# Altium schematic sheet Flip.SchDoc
size A3; Author: Power Lin; SheetNumber: 1; SheetTotal: 1; Website: wiki-power.com
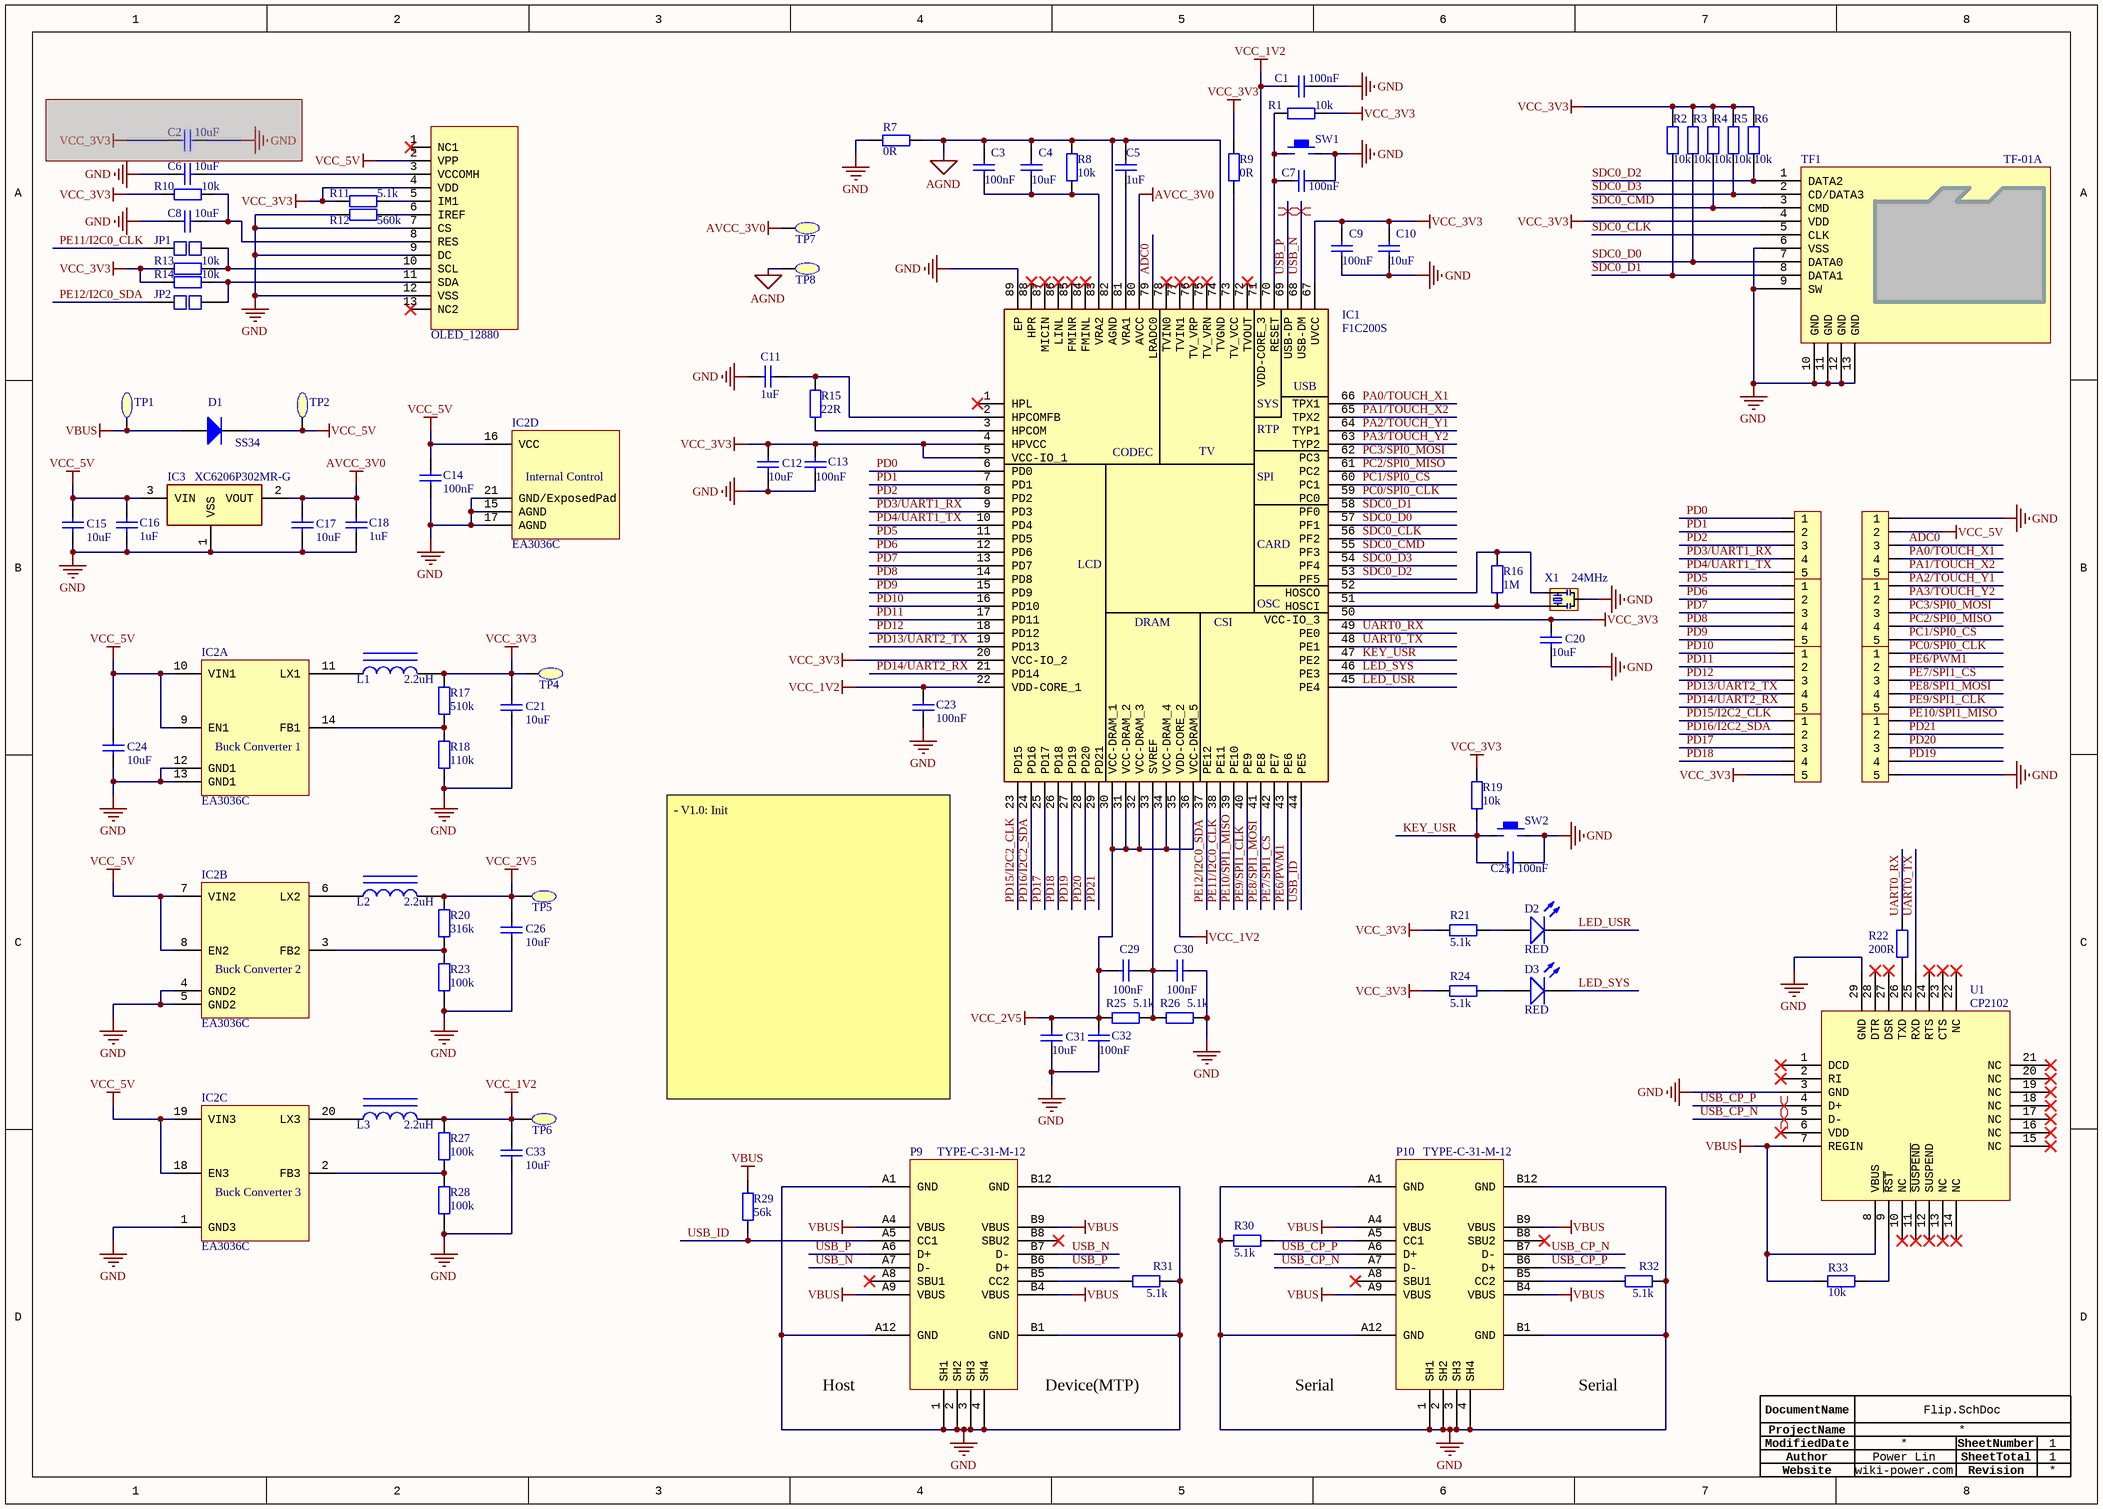
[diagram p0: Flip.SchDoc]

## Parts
C1  100nF  [CAP-0402]
C2  10uF  [CAP-0402]  (masked out: inside a compile mask, not in the netlist)
C3  100nF  [CAP-0402]
C4  10uF  [CAP-0402]
C5  1uF  [CAP-0402]
C6  10uF  [CAP-0402]
C7  100nF  [CAP-0402]
C8  10uF  [CAP-0402]
C9  100nF  [CAP-0402]
C10  10uF  [CAP-0402]
C11  1uF  [CAP-0402]
C12  10uF  [CAP-0402]
C13  100nF  [CAP-0402]
C14  100nF  [CAP-0402]
C15  10uF  [CAP-0402]
C16  1uF  [CAP-0402]
C17  10uF  [CAP-0402]
C18  1uF  [CAP-0402]
C20  10uF  [CAP-0402]
C21  10uF  [CAP-0402]
C23  100nF  [CAP-0402]
C24  10uF  [CAP-0402]
C25  100nF  [CAP-0402]
C26  10uF  [CAP-0402]
C29  100nF  [CAP-0402]
C30  100nF  [CAP-0402]
C31  10uF  [CAP-0402]
C32  100nF  [CAP-0402]
C33  10uF  [CAP-0402]
D1  SS34  [DO-214AC/SMA]
D2  RED  [LED-0402]
D3  RED  [LED-0402]
IC1  F1C200S  [QFN88P_10X10mm]
IC2  EA3036C  [QFN3mmx3mm-20]  (parts A,B,C,D of 4)
IC3  XC6206P302MR-G  [SOT-23-3]
JP1  Select  [选择焊点-0402]  (value not drawn)
JP2  Select  [选择焊点-0402]  (value not drawn)
L1  2.2uH  [L-1008]
L2  2.2uH  [L-1008]
L3  2.2uH  [L-1008]
M1  OLED_12880  [OLED_0.78INCH_12880]
P1  HDR1x5  [HDR1X5_2.54_180_BLANK]  (value not drawn)
P2  HDR1x5  [HDR1X5_2.54_180_BLANK]  (value not drawn)
P3  HDR1x5  [HDR1X5_2.54_180_BLANK]  (value not drawn)
P4  HDR1x5  [HDR1X5_2.54_180_BLANK]  (value not drawn)
P5  HDR1x5  [HDR1X5_2.54_180_BLANK]  (value not drawn)
P6  HDR1x5  [HDR1X5_2.54_180_BLANK]  (value not drawn)
P7  HDR1x5  [HDR1X5_2.54_180_BLANK]  (value not drawn)
P8  HDR1x5  [HDR1X5_2.54_180_BLANK]  (value not drawn)
P9  TYPE-C-31-M-12  [Type-C_16+4P]
P10  TYPE-C-31-M-12  [Type-C_16+4P]
R1  10k  [R-0402]
R2  10k  [R-0402]
R3  10k  [R-0402]
R4  10k  [R-0402]
R5  10k  [R-0402]
R6  10k  [R-0402]
R7  0R  [R-0402]
R8  10k  [R-0402]
R9  0R  [R-0402]
R10  10k  [R-0402]
R11  5.1k  [R-0402]
R12  560k  [R-0402]
R13  10k  [R-0402]
R14  10k  [R-0402]
R15  22R  [R-0402]
R16  1M  [R-0402]
R17  510k  [R-0402]
R18  110k  [R-0402]
R19  10k  [R-0402]
R20  316k  [R-0402]
R21  5.1k  [R-0402]
R22  200R  [R-0402]
R23  100k  [R-0402]
R24  5.1k  [R-0402]
R25  5.1k  [R-0402]
R26  5.1k  [R-0402]
R27  100k  [R-0402]
R28  100k  [R-0402]
R29  56k  [R-0402]
R30  5.1k  [R-0402]
R31  5.1k  [R-0402]
R32  5.1k  [R-0402]
R33  10k  [R-0402]
SW1  KEY  [KEY-4P-4.2*3.4*2.5]  (value not drawn)
SW2  KEY  [KEY-4P-4.2*3.4*2.5]  (value not drawn)
TF1  TF-01A  [TF_1]
TP1  TestPoint  [TestPoint]  (value not drawn)
TP2  TestPoint  [TestPoint]  (value not drawn)
TP4  TestPoint  [TestPoint]  (value not drawn)
TP5  TestPoint  [TestPoint]  (value not drawn)
TP6  TestPoint  [TestPoint]  (value not drawn)
TP7  TestPoint  [TestPoint]  (value not drawn)
TP8  TestPoint  [TestPoint]  (value not drawn)
U1  CP2102  [QFN28]
X1  24MHz  [SMD3213-3P]

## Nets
AGND: C3.1 C4.2 C5.1 IC1.74(TVGND) IC1.82(AGND) R7.1 R8.2 TP8.1
AVCC_3V0: C17.2 C18.1 IC1.80(AVCC) IC3.2(VOUT) TP7.1
GND: C1.1 C6.2 C7.1 C8.2 C9.2 C10.1 C11.1 C12.1 C13.1 C14.1 C15.1 C16.2 C17.1 C18.2 C20.1 C21.1 C23.1 C24.1 C25.1 C26.1 C30.2 C31.1 C32.1 C33.1 IC1.89(EP) IC2.1(GND3) IC2.4(GND2) IC2.5(GND2) IC2.12(GND1) IC2.13(GND1) IC2.15(AGND) IC2.17(AGND) IC2.21(GND/ExposedPad) IC3.1(VSS) M1.7(CS) M1.9(DC) M1.12(VSS) P2.1 P8.5 P9.1(SH1) P9.2(SH2) P9.3(SH3) P9.4(SH4) P9.A1(GND) P9.A12(GND) P9.B1(GND) P9.B12(GND) P10.1(SH1) P10.2(SH2) P10.3(SH3) P10.4(SH4) P10.A1(GND) P10.A12(GND) P10.B1(GND) P10.B12(GND) R7.2 R12.1 R18.1 R23.1 R26.2 R28.1 R30.2 R31.2 R32.2 SW1.2 SW2.2 TF1.6(VSS) TF1.9(SW) TF1.10(GND) TF1.11(GND) TF1.12(GND) TF1.13(GND) U1.3(GND) U1.29(GND) X1.2(GND)
VBUS: D1.1(A) P9.A4(VBUS) P9.A9(VBUS) P9.B4(VBUS) P9.B9(VBUS) P10.A4(VBUS) P10.A9(VBUS) P10.B4(VBUS) P10.B9(VBUS) R29.1 R33.2 TP1.1 U1.7(REGIN) U1.8(VBUS)
VCC_1V2: C1.2 C23.2 C33.2 IC1.22(VDD-CORE_1) IC1.35(VDD-CORE_2) IC1.71(VDD-CORE_3) L3.2 R27.2 TP6.1
VCC_2V5: C26.2 C29.1 C31.2 C32.2 IC1.30(VCC-DRAM_1) IC1.31(VCC-DRAM_2) IC1.32(VCC-DRAM_3) IC1.34(VCC-DRAM_4) IC1.36(VCC-DRAM_5) L2.2 R20.2 R25.1 TP5.1
VCC_3V3: C9.1 C10.2 C12.2 C13.2 C20.2 C21.2 IC1.4(HPVCC) IC1.5(VCC-IO_1) IC1.20(VCC-IO_2) IC1.50(VCC-IO_3) IC1.67(UVCC) L1.2 M1.4(VDD) P7.5 R1.2 R2.2 R3.2 R4.2 R5.2 R6.2 R9.2 R10.1 R11.1 R13.1 R14.1 R17.2 R19.2 R21.1 R24.1 TF1.4(VDD) TP4.1
VCC_5V: C14.2 C15.2 C16.1 C24.2 D1.2(K) IC2.7(VIN2) IC2.8(EN2) IC2.9(EN1) IC2.10(VIN1) IC2.16(VCC) IC2.18(EN3) IC2.19(VIN3) IC3.3(VIN) M1.2(VPP) P2.2 TP2.1
ADC0: IC1.79(LRADC0) P2.3
KEY_USR: C25.2 IC1.47(PE2) R19.1 SW2.1
LED_SYS: D3.K IC1.46(PE3)
LED_USR: D2.K IC1.45(PE4)
PA0/TOUCH_X1: IC1.66(TPX1) P2.4
PA1/TOUCH_X2: IC1.65(TPX2) P2.5
PA2/TOUCH_Y1: IC1.64(TYP1) P4.1
PA3/TOUCH_Y2: IC1.63(TYP2) P4.2
PC0/SPI0_CLK: IC1.59(PC0) P6.1
PC1/SPI0_CS: IC1.60(PC1) P4.5
PC2/SPI0_MISO: IC1.61(PC2) P4.4
PC3/SPI0_MOSI: IC1.62(PC3) P4.3
PD0: IC1.6(PD0) P1.1
PD1: IC1.7(PD1) P1.2
PD2: IC1.8(PD2) P1.3
PD3/UART1_RX: IC1.9(PD3) P1.4
PD4/UART1_TX: IC1.10(PD4) P1.5
PD5: IC1.11(PD5) P3.1
PD6: IC1.12(PD6) P3.2
PD7: IC1.13(PD7) P3.3
PD8: IC1.14(PD8) P3.4
PD9: IC1.15(PD9) P3.5
PD10: IC1.16(PD10) P5.1
PD11: IC1.17(PD11) P5.2
PD12: IC1.18(PD12) P5.3
PD13/UART2_TX: IC1.19(PD13) P5.4
PD14/UART2_RX: IC1.21(PD14) P5.5
PD15/I2C2_CLK: IC1.23(PD15) P7.1
PD16/I2C2_SDA: IC1.24(PD16) P7.2
PD17: IC1.25(PD17) P7.3
PD18: IC1.26(PD18) P7.4
PD19: IC1.27(PD19) P8.4
PD20: IC1.28(PD20) P8.3
PD21: IC1.29(PD21) P8.2
PE6/PWM1: IC1.43(PE6) P6.2
PE7/SPI1_CS: IC1.42(PE7) P6.3
PE8/SPI1_MOSI: IC1.41(PE8) P6.4
PE9/SPI1_CLK: IC1.40(PE9) P6.5
PE10/SPI1_MISO: IC1.39(PE10) P8.1
PE11/I2C0_CLK: IC1.38(PE11) JP1.1
PE12/I2C0_SDA: IC1.37(PE12) JP2.1
SDC0_CLK: IC1.56(PF2) TF1.5(CLK)
SDC0_CMD: IC1.55(PF3) R4.1 TF1.3(CMD)
SDC0_D0: IC1.57(PF1) R3.1 TF1.7(DATA0)
SDC0_D1: IC1.58(PF0) R2.1 TF1.8(DATA1)
SDC0_D2: IC1.53(PF5) R6.1 TF1.1(DATA2)
SDC0_D3: IC1.54(PF4) R5.1 TF1.2(CD/DATA3)
UART0_RX: IC1.49(PE0) R22.1
UART0_TX: IC1.48(PE1) U1.25(RXD)
USB_CP_N: P10.A7(D-) P10.B7(D-) U1.5(D-)
USB_CP_P: P10.A6(D+) P10.B6(D+) U1.4(D+)
USB_ID: IC1.44(PE5) P9.A5(CC1) R29.2
USB_N: IC1.68(USB-DM) P9.A7(D-) P9.B7(D-)
USB_P: IC1.69(USB-DP) P9.A6(D+) P9.B6(D+)
NetC3_2: C3.2 C4.1 IC1.83(VRA2) R8.1
NetC5_2: C5.2 IC1.81(VRA1)
NetC6_1: C6.1 M1.3(VCCOMH)
NetC7_2: C7.2 IC1.70(RESET) R1.1 SW1.1
NetC8_1: C8.1 M1.8(RES) R10.2
NetC11_2: C11.2 IC1.2(HPCOMFB) R15.2
NetC29_2: C29.2 C30.1 IC1.33(SVREF) R25.2 R26.1
NetD2_A: D2.A R21.2
NetD3_A: D3.A R24.2
NetIC1_3: IC1.3(HPCOM) R15.1
NetIC1_51: IC1.51(HOSCI) R16.1 X1.1(OSC1)
NetIC1_52: IC1.52(HOSCO) R16.2 X1.3(OSC2)
NetIC1_73: IC1.73(TV_VCC) R9.1
NetIC2_2: IC2.2(FB3) R27.1 R28.2
NetIC2_3: IC2.3(FB2) R20.1 R23.2
NetIC2_6: IC2.6(LX2) L2.1
NetIC2_11: IC2.11(LX1) L1.1
NetIC2_14: IC2.14(FB1) R17.1 R18.2
NetIC2_20: IC2.20(LX3) L3.1
NetJP1_2: JP1.2 M1.10(SCL) R13.2
NetJP2_2: JP2.2 M1.11(SDA) R14.2
NetM1_5: M1.5(IM1) R11.2
NetM1_6: M1.6(IREF) R12.2
NetP9_B5: P9.B5(CC2) R31.1
NetP10_A5: P10.A5(CC1) R30.1
NetP10_B5: P10.B5(CC2) R32.1
NetR22_2: R22.2 U1.26(TXD)
NetR33_1: R33.1 U1.9(~{RST})

Not connected (* = marked no-connect by the designer): IC1 1(HPL)* 72(TVOUT)* 75(TV_VRN)* 76(TV_VRP)* 77(TVIN1)* 78(TVIN0)* 84(FMINL)* 85(FMINR)* 86(LINL)* 87(MICIN)* 88(HPR)*; M1 1(NC1)* 13(NC2)*; P9 A8(SBU1)* B8(SBU2)*; P10 A8(SBU1)* B8(SBU2)*; U1 1(DCD)* 2(RI)* 6(VDD)* 10(NC)* 11(~{SUSPEND})* 12(SUSPEND)* 13(NC)* 14(NC)* 15(NC)* 16(NC)* 17(NC)* 18(NC)* 19(NC)* 20(NC)* 21(NC)* 22(NC)* 23(CTS)* 24(RTS)* 27(DSR)* 28(DTR)*

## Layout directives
differential pair: USB_CP_N, USB_CP_P, USB_N, USB_P

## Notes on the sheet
- - V1.0: Init
- (near P9) Host
- (near P9) Device(MTP)
- (near P10) Serial
- Serial
- Author
- DocumentName
- ModifiedDate
- ProjectName
- SheetNumber
- SheetTotal
- Website
- Revision

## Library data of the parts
C1-C18 C20 C21 C23-C26 C29-C33 = CAP: 贴片电容
D1 = DIODE: 肖特基二极管
D2 D3 = LED: 发光二极管; pin to pad: A>1 K>2
IC1 = F1C100S/F1C200S: SOC; Manufacturer_Name: Allwinner Technology
IC2 = EA3036C: EA3036 is a 3CH power management IC for applications powered by one Li-Ion battery or a DC 5V adapter.
IC3 = XC6206: LDO; Manufacturer_Name: Torex; Manufacturer_Part_Number: XC6206P122MR-G
JP1 JP2 = Select: 选择焊点
L1-L3 = INDUCTOR: SRN2512-2R2M
M1 = OLED_12880: OLED屏
P1-P8 = HDR1x5_2.54: Header; Manufacturer_Name: FCI Electronics; Manufacturer_Part_Number: 10129378-905001BLF
P9 P10 = USB_Type-C_16+4P: USB Type-C 座子
R1-R16 R19 R21 R22 R24-R26 R29-R33 = RES: 贴片电阻
R17 R18 = RES: RC0402FR-07510KL
R20 = RES: RC0402FR-07316KL
R23 R27 R28 = RES: RC0402FR-07100KL
SW1 SW2 = KEY: 按键开关
TF1 = TF卡座_8脚自弹: 与TF-01A封装相似则可替换
TP1 TP2 TP4-TP8 = TestPoint: 测试点
U1 = CP2102: CP2102-GMR
X1 = XTAL: 村田无源晶振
